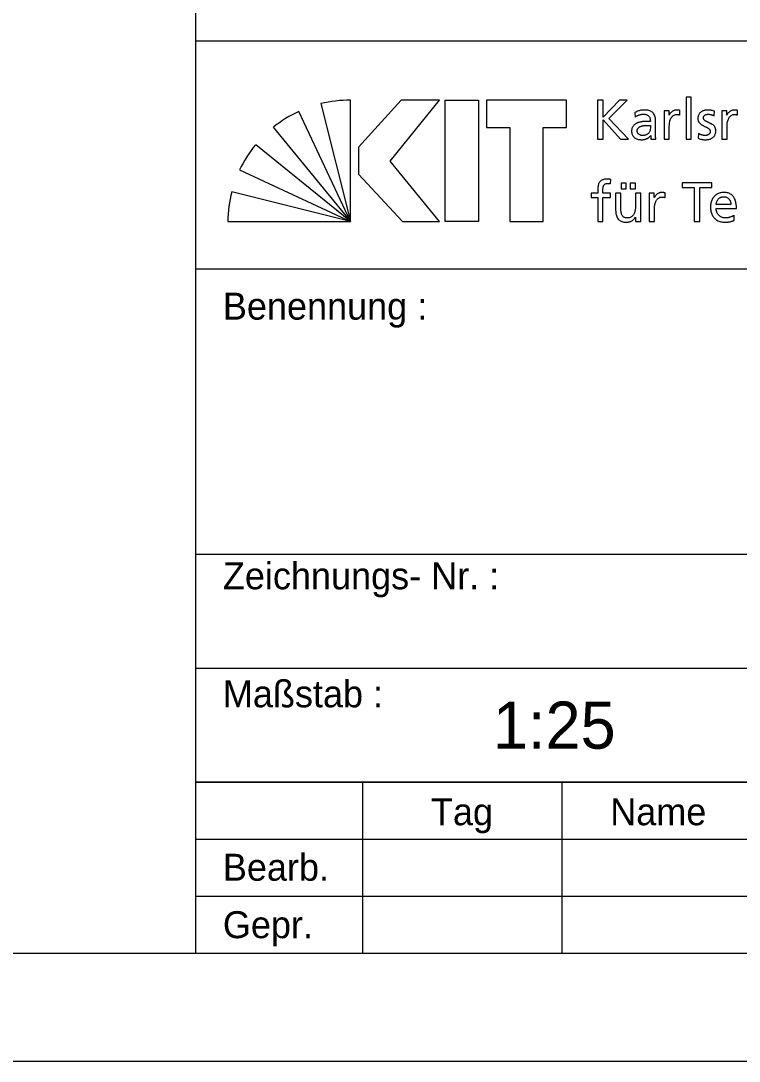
# Model space of a CAD drawing. Extents: x 0 to 10.5, y 0 to 7.4.
# Drawn here: x 7.875 to 9.208, y 0 to 1.929 of the extents above; entities that cross this region are included whole.
import ezdxf

# ---------------------------------------------------------------- set-up
doc = ezdxf.new("R2010")
doc.units = 0
doc.layers.add('90_Plankopf', color=7, linetype='Continuous')

msp = doc.modelspace()

# ---------------------------------------------------------------- linework, layer by layer
at = {"layer": '90_Plankopf'}
for p, q in [((8.2001, 1.892), (8.2001, 2.2093)), ((8.2001, 1.892), (10.3, 1.892)), ((8.4319, 1.7756), (8.487, 1.5569)), ((8.487, 1.5569), (8.487, 1.7819)), ((8.9453, 1.7819), (8.9453, 1.7099)), ((8.487, 1.5569), (8.3909, 1.7611)), ((9.0145, 1.7588), (9.015, 1.7505)), ((9.0982, 1.7544), (9.0982, 1.763)), ((9.1614, 1.7532), (9.1623, 1.7617)), ((9.2053, 1.7544), (9.2053, 1.763)), ((9.053, 1.7202), (9.053, 1.742)), ((8.3436, 1.7319), (8.487, 1.5569)), ((9.0433, 1.735), (9.0433, 1.7303)), ((9.1325, 1.7202), (9.1319, 1.7115)), ((8.487, 1.5569), (8.3109, 1.6994)), ((8.9453, 1.7099), (8.9556, 1.7099)), ((8.9877, 1.7099), (9.0027, 1.7099)), ((8.281, 1.6526), (8.487, 1.5569)), ((8.9694, 1.6271), (8.9698, 1.6349)), ((8.487, 1.5569), (8.2665, 1.6119)), ((9.0707, 1.6014), (9.0707, 1.61)), ((9.1927, 1.5883), (9.1654, 1.5883)), ((9.1654, 1.5811), (9.203, 1.5811)), ((9.199, 1.5591), (9.199, 1.5688)), ((8.2591, 1.5569), (8.487, 1.5569)), ((8.2001, 1.469), (10.3, 1.469)), ((8.2001, 0.9403), (10.3, 0.9403)), ((8.2001, 0.7288), (10.3, 0.7288)), ((8.2001, 0.5172), (10.3, 0.5172)), ((8.2001, 0.5172), (10.3, 0.5172)), ((8.2001, 0.5172), (10.3, 0.5172)), ((8.2001, 0.5172), (10.3, 0.5172)), ((8.2001, 0.2), (8.2001, 0.5172)), ((8.5089, 0.5172), (8.5089, 0.2)), ((8.8795, 0.2), (8.8795, 0.5172)), ((8.2001, 0.4115), (9.25, 0.4115)), ((8.2001, 0.3058), (9.25, 0.3058)), ((8.2001, 0.2), (10.3, 0.2)), ((8.2001, 0.2), (10.3, 0.2))]:
    msp.add_line(p, q, dxfattribs=at)
for points in [[(0, 0), (10.5, 0), (10.5, 7.425), (0, 7.425)], [(0.2, 0.2), (10.3, 0.2), (10.3, 7.225), (0.2, 7.225)], [(8.6517, 1.7819), (8.5809, 1.7819), (8.5018, 1.6947), (8.5018, 1.6445), (8.5835, 1.5569), (8.6521, 1.5569), (8.5606, 1.6688)], [(8.7243, 1.7819), (8.7243, 1.5569), (8.6626, 1.5569), (8.6626, 1.7819)], [(8.7391, 1.7819), (8.7391, 1.7313), (8.7826, 1.7313), (8.7826, 1.5569), (8.8443, 1.5569), (8.8443, 1.7313), (8.8878, 1.7313), (8.8878, 1.7819)]]:
    msp.add_lwpolyline(points, close=True, dxfattribs=at)
for points in [[(8.2001, 0.5172), (8.2001, 1.892)], [(9.0027, 1.7099), (8.9662, 1.7479), (9, 1.7819), (8.9863, 1.7819), (8.9556, 1.7502), (8.9556, 1.7819), (8.9453, 1.7819)], [(9.1095, 1.7099), (9.1192, 1.7099), (9.1192, 1.7873), (9.1095, 1.7873), (9.1095, 1.7099)], [(9.0781, 1.7544), (9.0779, 1.7544), (9.0779, 1.7625), (9.0688, 1.7625), (9.0688, 1.7099), (9.0785, 1.7099), (9.0785, 1.7338)], [(9.1852, 1.7544), (9.185, 1.7544), (9.185, 1.7625), (9.1759, 1.7625), (9.1759, 1.7099), (9.1856, 1.7099), (9.1856, 1.7338)], [(8.9556, 1.7099), (8.9556, 1.7452), (8.9877, 1.7099)], [(9.0441, 1.7167), (9.0443, 1.7167), (9.0443, 1.7099), (9.0534, 1.7099)], [(8.9889, 1.6279), (8.9889, 1.6176), (8.9986, 1.6176), (8.9986, 1.6279), (8.9889, 1.6279)], [(9.0058, 1.6279), (9.0058, 1.6176), (9.0155, 1.6176), (9.0155, 1.6279), (9.0058, 1.6279)], [(9.1248, 1.5569), (9.1351, 1.5569), (9.1351, 1.6198), (9.1575, 1.6198), (9.1575, 1.6289), (9.1024, 1.6289), (9.1024, 1.6198), (9.1248, 1.6198), (9.1248, 1.5569)], [(8.9456, 1.6144), (8.9456, 1.6095), (8.9333, 1.6095), (8.9333, 1.6017), (8.9456, 1.6017), (8.9456, 1.5569), (8.9553, 1.5569), (8.9553, 1.6017), (8.9693, 1.6017), (8.9693, 1.6095), (8.9553, 1.6095), (8.9553, 1.6152)], [(8.9886, 1.5823), (8.9886, 1.6095), (8.9789, 1.6095), (8.9789, 1.5783)], [(9.0254, 1.5569), (9.0254, 1.6095), (9.0157, 1.6095), (9.0157, 1.5852)], [(9.0506, 1.6014), (9.0504, 1.6014), (9.0504, 1.6095), (9.0413, 1.6095), (9.0413, 1.5569), (9.051, 1.5569), (9.051, 1.5808)], [(9.0158, 1.5653), (9.016, 1.5653), (9.016, 1.5569), (9.0254, 1.5569)], [(10.3, 0.5172), (8.2001, 0.5172)], [(8.2001, 0.5172), (8.2001, 0.5172)], [(8.2001, 0.2), (10.3, 0.2)]]:
    msp.add_lwpolyline(points, dxfattribs=at)
for centre, start, end in [((8.4862, 1.5437), 89.8053, 103.1895), ((8.4916, 1.5452), 115.0126, 128.3968), ((8.4954, 1.5488), 140.7898, 154.174), ((8.4973, 1.5532), 165.7222, 179.1064)]:
    msp.add_arc(centre, 0.2382, start, end, dxfattribs=at)
for points in [[(9.053, 1.742), (9.053, 1.7468), (9.0523, 1.7508), (9.0509, 1.754), (9.0494, 1.7572), (9.0471, 1.7597), (9.044, 1.7613), (9.0409, 1.7629), (9.0368, 1.7637), (9.0318, 1.7637), (9.0285, 1.7637), (9.0254, 1.7633), (9.0225, 1.7624), (9.0196, 1.7615), (9.0169, 1.7603), (9.0145, 1.7588)], [(9.015, 1.7505), (9.0163, 1.7516), (9.0178, 1.7526), (9.0195, 1.7534), (9.0212, 1.7542), (9.0229, 1.7548), (9.0248, 1.7553), (9.0266, 1.7557), (9.0284, 1.7559), (9.0303, 1.7559), (9.0335, 1.7559), (9.0361, 1.7554), (9.038, 1.7544), (9.0399, 1.7533), (9.0412, 1.7518), (9.0421, 1.7498), (9.0429, 1.7477), (9.0433, 1.7452), (9.0433, 1.7422)], [(9.0982, 1.763), (9.0975, 1.7632), (9.0969, 1.7633), (9.0963, 1.7634), (9.0956, 1.7635), (9.095, 1.7636), (9.0943, 1.7636), (9.0936, 1.7637), (9.0927, 1.7637), (9.0918, 1.7637), (9.0899, 1.7637), (9.0881, 1.7633), (9.0863, 1.7625), (9.0846, 1.7617), (9.083, 1.7606), (9.0815, 1.7592), (9.0801, 1.7578), (9.0789, 1.7562), (9.0781, 1.7544)], [(9.1623, 1.7617), (9.1604, 1.7623), (9.1585, 1.7628), (9.1565, 1.7631), (9.1546, 1.7635), (9.1525, 1.7637), (9.1502, 1.7637), (9.1476, 1.7637), (9.1452, 1.7634), (9.1429, 1.7628), (9.1407, 1.7621), (9.1387, 1.7611), (9.137, 1.7598), (9.1353, 1.7584), (9.134, 1.7567), (9.1331, 1.7547), (9.1321, 1.7527), (9.1316, 1.7503), (9.1316, 1.7476), (9.1316, 1.7455), (9.1321, 1.7436), (9.1329, 1.7421), (9.1337, 1.7406), (9.1348, 1.7392), (9.1362, 1.7381), (9.1375, 1.737), (9.139, 1.736), (9.1406, 1.7351), (9.1422, 1.7343), (9.1438, 1.7334), (9.1455, 1.7327), (9.1471, 1.7319), (9.1486, 1.7311), (9.1499, 1.7303), (9.1513, 1.7295), (9.1524, 1.7286), (9.1532, 1.7276), (9.154, 1.7266), (9.1544, 1.7254), (9.1544, 1.724), (9.1544, 1.7226), (9.1541, 1.7214), (9.1535, 1.7205), (9.1529, 1.7195), (9.1521, 1.7187), (9.1511, 1.7181), (9.1502, 1.7175), (9.1491, 1.7171), (9.148, 1.7169), (9.1468, 1.7166), (9.1456, 1.7165), (9.1445, 1.7165), (9.1436, 1.7165), (9.1424, 1.7166), (9.141, 1.7169), (9.1396, 1.7172), (9.1382, 1.7176), (9.1367, 1.7182), (9.1352, 1.7187), (9.1338, 1.7194), (9.1325, 1.7202)], [(9.1319, 1.7115), (9.1342, 1.7104), (9.1365, 1.7096), (9.139, 1.7092), (9.1414, 1.7088), (9.1439, 1.7086), (9.1464, 1.7087), (9.1488, 1.7087), (9.151, 1.709), (9.1532, 1.7096), (9.1554, 1.7103), (9.1574, 1.7113), (9.1591, 1.7126), (9.1608, 1.714), (9.1622, 1.7157), (9.1632, 1.7178), (9.1642, 1.7198), (9.1647, 1.7223), (9.1648, 1.7251), (9.1647, 1.7275), (9.1643, 1.7295), (9.1635, 1.7311), (9.1627, 1.7328), (9.1616, 1.7342), (9.1602, 1.7354), (9.1589, 1.7366), (9.1574, 1.7375), (9.1558, 1.7384), (9.1542, 1.7392), (9.1525, 1.74), (9.1509, 1.7407), (9.1493, 1.7414), (9.1478, 1.7421), (9.1465, 1.7429), (9.1451, 1.7437), (9.144, 1.7446), (9.1432, 1.7457), (9.1424, 1.7467), (9.142, 1.748), (9.1419, 1.7495), (9.142, 1.751), (9.1424, 1.7522), (9.1433, 1.7531), (9.1441, 1.7541), (9.1452, 1.7548), (9.1466, 1.7552), (9.148, 1.7557), (9.1496, 1.7559), (9.1512, 1.7559), (9.1518, 1.7559), (9.1526, 1.7558), (9.1535, 1.7557), (9.1544, 1.7555), (9.1554, 1.7553), (9.1564, 1.7551), (9.1574, 1.7548), (9.1584, 1.7545), (9.1593, 1.7542), (9.1602, 1.7539), (9.1609, 1.7536), (9.1614, 1.7532)], [(9.2053, 1.763), (9.2046, 1.7632), (9.204, 1.7633), (9.2034, 1.7634), (9.2028, 1.7635), (9.2021, 1.7636), (9.2014, 1.7636), (9.2007, 1.7637), (9.1999, 1.7637), (9.1989, 1.7637), (9.197, 1.7637), (9.1952, 1.7633), (9.1934, 1.7625), (9.1917, 1.7617), (9.1901, 1.7606), (9.1887, 1.7592), (9.1872, 1.7578), (9.1861, 1.7562), (9.1852, 1.7544)], [(9.0433, 1.7422), (9.042, 1.7423), (9.0409, 1.7423), (9.0398, 1.7423), (9.0387, 1.7424), (9.0376, 1.7424), (9.0365, 1.7424), (9.0354, 1.7424), (9.0342, 1.7424), (9.033, 1.7424), (9.0309, 1.7424), (9.0288, 1.7422), (9.0266, 1.7419), (9.0244, 1.7415), (9.0222, 1.7409), (9.02, 1.7401), (9.0179, 1.7393), (9.016, 1.7382), (9.0142, 1.7369), (9.0125, 1.7355), (9.0111, 1.7339), (9.0101, 1.7319), (9.0091, 1.73), (9.0086, 1.7277), (9.0085, 1.7251), (9.0086, 1.7213), (9.0094, 1.7181), (9.011, 1.7157), (9.0126, 1.7133), (9.0149, 1.7115), (9.0178, 1.7104), (9.0207, 1.7092), (9.024, 1.7087), (9.0278, 1.7087), (9.03, 1.7087), (9.032, 1.7089), (9.0338, 1.7095), (9.0355, 1.71), (9.0371, 1.7107), (9.0384, 1.7115), (9.0398, 1.7123), (9.0409, 1.7132), (9.0419, 1.7141), (9.0428, 1.715), (9.0435, 1.7159), (9.0441, 1.7167)], [(9.0785, 1.7338), (9.0785, 1.7383), (9.0791, 1.7421), (9.0803, 1.7453), (9.0815, 1.7485), (9.0831, 1.7509), (9.0853, 1.7527), (9.0874, 1.7544), (9.0899, 1.7553), (9.0928, 1.7553), (9.0937, 1.7553), (9.0945, 1.7552), (9.0955, 1.7551), (9.0964, 1.755), (9.0973, 1.7547), (9.0982, 1.7544)], [(9.1856, 1.7338), (9.1856, 1.7383), (9.1862, 1.7421), (9.1874, 1.7453), (9.1886, 1.7485), (9.1902, 1.7509), (9.1924, 1.7527), (9.1945, 1.7544), (9.197, 1.7553), (9.1999, 1.7553), (9.2008, 1.7553), (9.2017, 1.7552), (9.2026, 1.7551), (9.2035, 1.755), (9.2044, 1.7547), (9.2053, 1.7544)], [(9.0433, 1.7303), (9.0433, 1.7277), (9.0427, 1.7253), (9.0416, 1.7233), (9.0405, 1.7212), (9.0389, 1.7195), (9.0367, 1.7183), (9.0345, 1.7171), (9.0318, 1.7165), (9.0286, 1.7165), (9.0275, 1.7165), (9.0264, 1.7167), (9.0252, 1.717), (9.0241, 1.7174), (9.023, 1.718), (9.0221, 1.7187), (9.0211, 1.7194), (9.0203, 1.7203), (9.0197, 1.7214), (9.0192, 1.7224), (9.0189, 1.7237), (9.0188, 1.7251), (9.0189, 1.7269), (9.0193, 1.7285), (9.0202, 1.7297), (9.0211, 1.7309), (9.0223, 1.7319), (9.0238, 1.7326), (9.0252, 1.7334), (9.0267, 1.7339), (9.0284, 1.7343), (9.03, 1.7347), (9.0316, 1.7349), (9.0332, 1.735), (9.0347, 1.7351), (9.036, 1.7352), (9.0371, 1.7352), (9.0381, 1.7352), (9.0392, 1.7351), (9.0402, 1.7351), (9.0412, 1.735), (9.0423, 1.735), (9.0433, 1.735)], [(9.0534, 1.7099), (9.0533, 1.7104), (9.0533, 1.7111), (9.0532, 1.7119), (9.0531, 1.7128), (9.0531, 1.7139), (9.0531, 1.7152), (9.053, 1.7166), (9.053, 1.7182), (9.053, 1.7202)], [(8.9698, 1.6349), (8.9688, 1.6351), (8.9678, 1.6352), (8.9667, 1.6353), (8.9656, 1.6355), (8.9645, 1.6355), (8.9633, 1.6355), (8.9597, 1.6355), (8.9568, 1.635), (8.9545, 1.634), (8.9522, 1.633), (8.9504, 1.6316), (8.9491, 1.6297), (8.9478, 1.6279), (8.9469, 1.6257), (8.9464, 1.6231), (8.9459, 1.6205), (8.9456, 1.6176), (8.9456, 1.6144)], [(8.9553, 1.6152), (8.9553, 1.617), (8.9554, 1.6186), (8.9556, 1.6202), (8.9558, 1.6217), (8.9563, 1.623), (8.9569, 1.6241), (8.9575, 1.6252), (8.9585, 1.6261), (8.9597, 1.6267), (8.961, 1.6274), (8.9626, 1.6277), (8.9647, 1.6277), (8.9656, 1.6277), (8.9664, 1.6276), (8.9672, 1.6275), (8.9681, 1.6274), (8.9688, 1.6273), (8.9694, 1.6271)], [(9.0707, 1.61), (9.07, 1.6102), (9.0694, 1.6103), (9.0688, 1.6104), (9.0682, 1.6105), (9.0675, 1.6106), (9.0668, 1.6107), (9.0661, 1.6107), (9.0652, 1.6108), (9.0643, 1.6108), (9.0624, 1.6107), (9.0606, 1.6103), (9.0588, 1.6095), (9.0571, 1.6088), (9.0555, 1.6077), (9.0541, 1.6062), (9.0526, 1.6048), (9.0515, 1.6032), (9.0506, 1.6014)], [(9.051, 1.5808), (9.051, 1.5853), (9.0516, 1.5891), (9.0528, 1.5923), (9.054, 1.5955), (9.0556, 1.598), (9.0578, 1.5997), (9.0599, 1.6014), (9.0624, 1.6023), (9.0653, 1.6023), (9.0662, 1.6023), (9.0671, 1.6023), (9.068, 1.6021), (9.0689, 1.602), (9.0698, 1.6017), (9.0707, 1.6014)], [(9.203, 1.5811), (9.203, 1.5853), (9.2026, 1.5892), (9.2018, 1.5928), (9.201, 1.5964), (9.1998, 1.5996), (9.198, 1.6023), (9.1962, 1.6049), (9.1938, 1.607), (9.1908, 1.6085), (9.1878, 1.61), (9.1841, 1.6107), (9.1798, 1.6108), (9.176, 1.6107), (9.1727, 1.6101), (9.1696, 1.6088), (9.1666, 1.6075), (9.164, 1.6057), (9.1619, 1.6033), (9.1597, 1.6009), (9.158, 1.5981), (9.1569, 1.5949), (9.1557, 1.5916), (9.1551, 1.5881), (9.1551, 1.5841), (9.1551, 1.5798), (9.1557, 1.576), (9.1567, 1.5725), (9.1578, 1.569), (9.1595, 1.566), (9.1617, 1.5635), (9.164, 1.561), (9.1668, 1.5591), (9.1702, 1.5577), (9.1737, 1.5564), (9.1777, 1.5557), (9.1824, 1.5557), (9.1852, 1.5557), (9.1877, 1.5559), (9.1897, 1.5563), (9.1917, 1.5566), (9.1935, 1.5571), (9.1949, 1.5576), (9.1964, 1.5581), (9.1977, 1.5586), (9.199, 1.5591)], [(9.1654, 1.5883), (9.1656, 1.59), (9.166, 1.5917), (9.1666, 1.5934), (9.1672, 1.5951), (9.1681, 1.5967), (9.1692, 1.5982), (9.1703, 1.5996), (9.1717, 1.6007), (9.1735, 1.6016), (9.1752, 1.6025), (9.1772, 1.6029), (9.1796, 1.6029), (9.1817, 1.6029), (9.1835, 1.6025), (9.1851, 1.6018), (9.1868, 1.601), (9.1881, 1.6), (9.1893, 1.5986), (9.1904, 1.5973), (9.1912, 1.5957), (9.1918, 1.594), (9.1924, 1.5922), (9.1927, 1.5903), (9.1927, 1.5883)], [(9.0157, 1.5852), (9.0157, 1.582), (9.0154, 1.579), (9.0148, 1.5764), (9.0141, 1.5737), (9.0132, 1.5715), (9.0118, 1.5695), (9.0105, 1.5676), (9.0089, 1.5661), (9.0069, 1.5651), (9.0048, 1.564), (9.0025, 1.5635), (8.9997, 1.5635), (8.9969, 1.5637), (8.9947, 1.5645), (8.9931, 1.5659), (8.9914, 1.5673), (8.9903, 1.5694), (8.9896, 1.5721), (8.9889, 1.5748), (8.9886, 1.5782), (8.9886, 1.5823)], [(8.9789, 1.5783), (8.9789, 1.5735), (8.9796, 1.5695), (8.9809, 1.5661), (8.9823, 1.5628), (8.9845, 1.5602), (8.9874, 1.5584), (8.9903, 1.5566), (8.994, 1.5557), (8.9986, 1.5557), (9.001, 1.5557), (9.0034, 1.5561), (9.0057, 1.5568), (9.0079, 1.5576), (9.0099, 1.5587), (9.0117, 1.5601), (9.0134, 1.5616), (9.0148, 1.5633), (9.0158, 1.5653)], [(9.199, 1.5688), (9.1984, 1.5683), (9.1975, 1.5677), (9.1963, 1.5671), (9.1952, 1.5665), (9.1939, 1.566), (9.1924, 1.5654), (9.1909, 1.5649), (9.1893, 1.5644), (9.1877, 1.5641), (9.186, 1.5637), (9.1844, 1.5635), (9.1828, 1.5635), (9.1804, 1.5635), (9.1783, 1.5639), (9.1762, 1.5648), (9.1741, 1.5656), (9.1723, 1.5668), (9.1707, 1.5684), (9.169, 1.5699), (9.1678, 1.5718), (9.1668, 1.5739), (9.1659, 1.5761), (9.1655, 1.5784), (9.1654, 1.5811)]]:
    msp.add_open_spline(points, degree=3, dxfattribs=at)

# ---------------------------------------------------------------- texts
for s, height, p in [('Benennung :', 0.05, (8.25, 1.375)), ('Zeichnungs- Nr. :', 0.05, (8.25, 0.875)), ('Maßstab :', 0.05, (8.25, 0.6562)), ('1:25    ', 0.0875, (8.7512, 0.5794)), ('Tag', 0.05, (8.6361, 0.4375)), ('Name', 0.05, (8.9688, 0.4375)), ('Bearb.', 0.05, (8.25, 0.3346)), ('Gepr.', 0.05, (8.25, 0.2281))]:
    msp.add_text(s, height=height, dxfattribs=at).set_placement(p)

doc.saveas('drawing.dxf')
